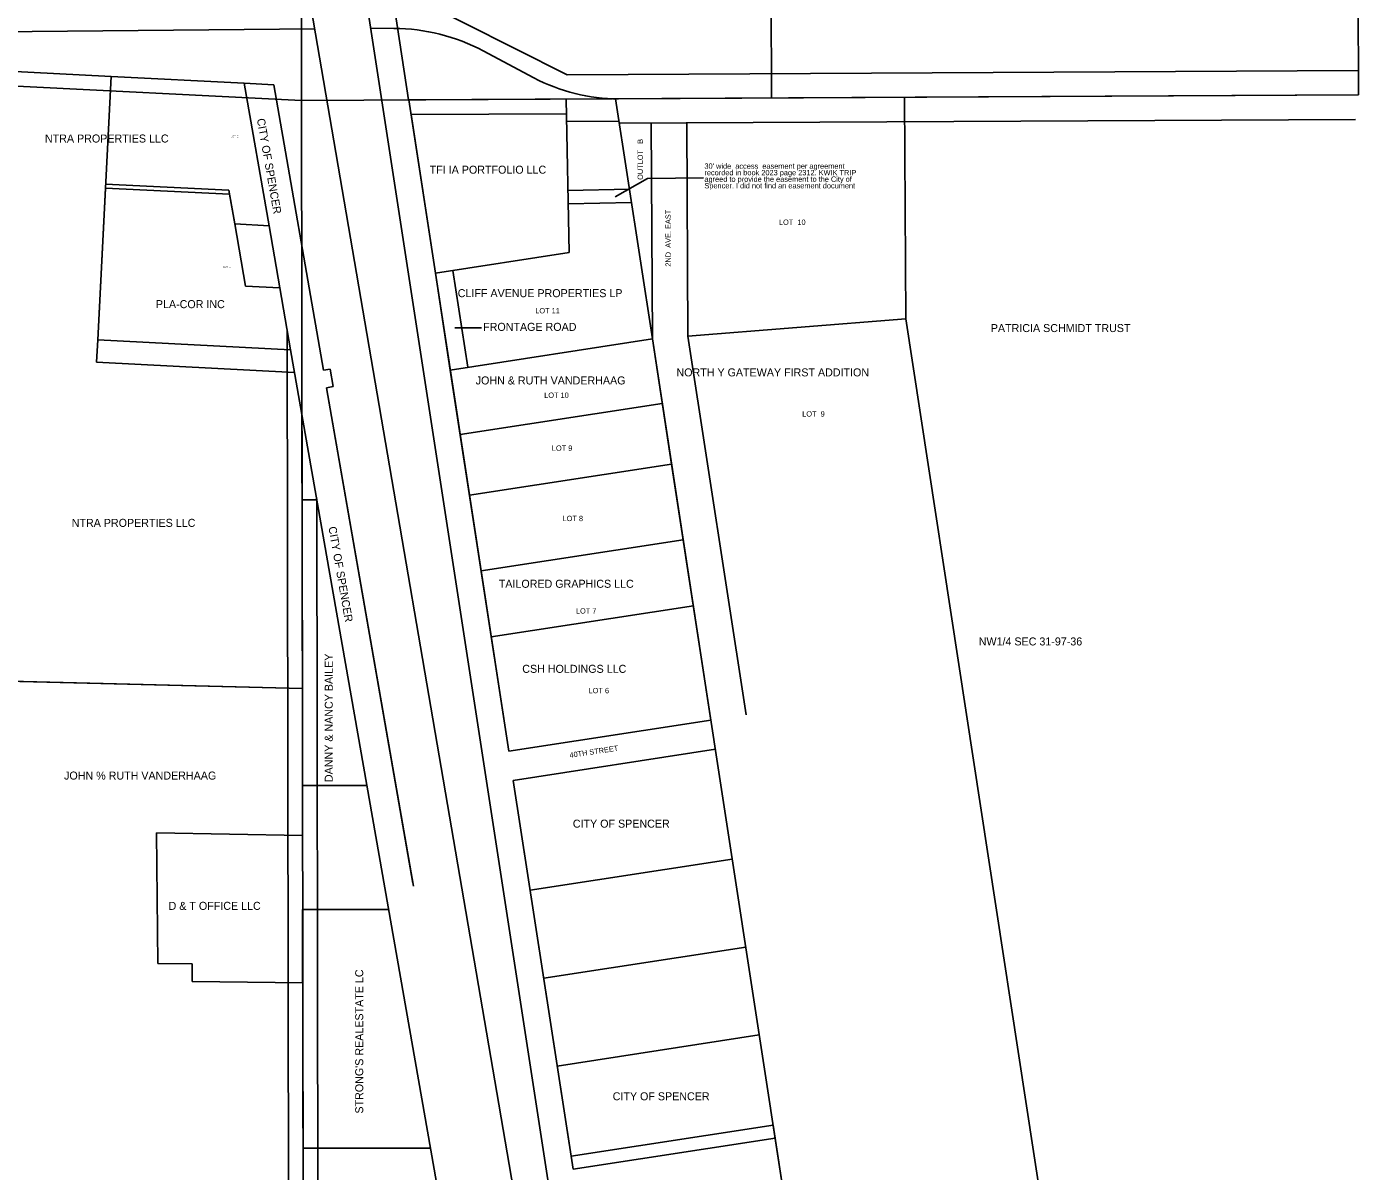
# Model space of a CAD drawing. Extents: x 11521219 to 11528920, y 9587418 to 9599499.
# Drawn here: x 11525924 to 11528920, y 9591637 to 9594212 of the extents above; entities that cross this region are included whole.
import ezdxf

# ---------------------------------------------------------------- set-up
doc = ezdxf.new("R2010")
doc.units = 0
for name, color, linetype in [('Alignment', 7, 'Continuous'), ('DisROW Existing', 7, 'Continuous'), ('DisROW Lot Lines', 7, 'Continuous'), ('DisROW Property Lines', 7, 'Continuous'), ('DisROW Survey', 7, 'Continuous'), ('Section Lines', 7, 'Continuous'), ('Text', 7, 'Continuous')]:
    doc.layers.add(name, color=color, linetype=linetype)

msp = doc.modelspace()

# ---------------------------------------------------------------- linework, layer by layer
at = {"layer": 'Alignment'}
for p, q in [((11527252.3, 9590607.6), (11526645, 9594551)), ((11527165.7, 9590741), (11526539.8, 9594397.6)), ((11523871.9, 9594181.4), (11526572.4, 9594207.2)), ((11526697.8, 9594208.3), (11526750.3, 9594208.1)), ((11526951.3, 9594157.5), (11527065.3, 9594096.7)), ((11527255.7, 9594049.6), (11528919.9, 9594058.4))]:
    msp.add_line(p, q, dxfattribs=at)
for centre, radius, start, end in [((11526748.9, 9593778.1), 430, 61.9248, 89.8166), ((11527256.1, 9594459.6), 410, 242.2771, 269.9507)]:
    msp.add_arc(centre, radius, start, end, dxfattribs=at)
at = {"layer": 'DisROW Existing'}
for p, q in [((11526743.9, 9594303.4), (11527140.1, 9594104)), ((11525869.3, 9594112.3), (11526113.9, 9594099.8)), ((11527140.1, 9594104), (11528919.7, 9594113.4)), ((11526113.9, 9594099.8), (11526413.5, 9594084.6)), ((11526413.5, 9594084.6), (11526480.2, 9594081.1)), ((11526480.2, 9594081.1), (11526592, 9593439.4)), ((11526788.9, 9594014.2), (11527138.5, 9594016)), ((11526843.7, 9593657.6), (11526788.9, 9594014.2)), ((11527138.5, 9594016), (11527138.8, 9593999)), ((11527256.5, 9593999.6), (11527138.8, 9593999)), ((11527257.3, 9593994.6), (11528913.3, 9594003.4)), ((11526877.2, 9593439.7), (11526843.7, 9593657.6)), ((11526510.2, 9593529.3), (11526513.1, 9591401.2)), ((11526592, 9593439.4), (11526606.7, 9593441.9)), ((11526606.7, 9593441.9), (11526613.7, 9593402.5)), ((11526877.2, 9593439.7), (11527008.9, 9592582.2)), ((11526613.7, 9593402.5), (11526598.9, 9593400)), ((11526598.9, 9593400), (11526794.2, 9592278.7)), ((11526576.8, 9593149.7), (11526579.1, 9591401.4)), ((11527463.5, 9592651.9), (11527008.9, 9592582.2)), ((11527018.9, 9592516.8), (11527473.6, 9592586.7)), ((11527153.2, 9591642.1), (11527018.9, 9592516.8))]:
    msp.add_line(p, q, dxfattribs=at)
at = {"layer": 'DisROW Lot Lines'}
for p, q in [((11526083.9, 9593507.3), (11526113.9, 9594099.8)), ((11526113.9, 9594099.8), (11526413.5, 9594084.6)), ((11526413.5, 9594084.6), (11526469.4, 9593764.4)), ((11527137.8, 9594049), (11527144.5, 9593703.8)), ((11527331.8, 9593509.7), (11527248.9, 9594049.6)), ((11527329.2, 9593995), (11527331.8, 9593509.7)), ((11527409.2, 9593995.4), (11527411.8, 9593516)), ((11526379.2, 9593844.1), (11526101.6, 9593858.1)), ((11526379.2, 9593844.1), (11526392.5, 9593768.2)), ((11526469.4, 9593764.4), (11526392.5, 9593768.2)), ((11526469.4, 9593764.4), (11526517.9, 9593485.1)), ((11527144.5, 9593703.8), (11526843.7, 9593657.6)), ((11526843.7, 9593657.6), (11527008.9, 9592582.2)), ((11527901.7, 9593554.7), (11527411.8, 9593515.9)), ((11526517.9, 9593485.1), (11526083.9, 9593507.3)), ((11527331.8, 9593509.7), (11526877.2, 9593439.7)), ((11527375.1, 9593227.9), (11527331.8, 9593509.7)), ((11527331.8, 9593509.7), (11527463.5, 9592651.9)), ((11527411.8, 9593516), (11527542.6, 9592664)), ((11527354.1, 9593364.4), (11526899.5, 9593294.4)), ((11527375.1, 9593227.9), (11526920.4, 9593158.1)), ((11527654.7, 9591407), (11527375.1, 9593227.9)), ((11526946.5, 9592988.1), (11527401.2, 9593057.9)), ((11526969.3, 9592839.8), (11527424, 9592909.6)), ((11527463.5, 9592651.9), (11527008.9, 9592582.2)), ((11527018.9, 9592516.8), (11527473.6, 9592586.7)), ((11527018.9, 9592516.8), (11527153.2, 9591642.1)), ((11527056.9, 9592269.8), (11527511.5, 9592339.6)), ((11527087.2, 9592072.1), (11527541.9, 9592141.9)), ((11527117.6, 9591874.4), (11527572.2, 9591944.2)), ((11527153.2, 9591642.1), (11527607.9, 9591712))]:
    msp.add_line(p, q, dxfattribs=at)
at = {"layer": 'DisROW Property Lines'}
for p, q in [((11528919.9, 9594058.4), (11528913, 9596702.5)), ((11526743.9, 9594303.4), (11526783.4, 9594047.1)), ((11525869.3, 9594112.3), (11526113.9, 9594099.8)), ((11526113.9, 9594099.8), (11526413.5, 9594084.6)), ((11526413.5, 9594084.6), (11526469.4, 9593764.4)), ((11526413.5, 9594084.6), (11526480.2, 9594081.1)), ((11526480.2, 9594081.1), (11526592, 9593439.4)), ((11526783.4, 9594047.1), (11528919.9, 9594058.4)), ((11526783.9, 9594047.1), (11526843.7, 9593657.6)), ((11527144.5, 9593703.8), (11527137.8, 9594049)), ((11527248.9, 9594049.6), (11527331.8, 9593509.7)), ((11527901.7, 9593554.7), (11527899, 9594053)), ((11527138.8, 9593999), (11527256.5, 9593999.6)), ((11526101.2, 9593849.1), (11526083.9, 9593507.3)), ((11526380.8, 9593834.9), (11526101.2, 9593849.1)), ((11526380.8, 9593834.9), (11526392.5, 9593768.2)), ((11526416.8, 9593628.7), (11526392.5, 9593768.2)), ((11526469.4, 9593764.4), (11526493.6, 9593624.9)), ((11526843.7, 9593657.6), (11527144.5, 9593703.8)), ((11526877.2, 9593439.7), (11526843.7, 9593657.6)), ((11526916.7, 9593445.8), (11526883.2, 9593663.6)), ((11526493.6, 9593624.9), (11526416.8, 9593628.7)), ((11526493.6, 9593624.9), (11526517.9, 9593485.1)), ((11528231, 9591410.6), (11527901.7, 9593554.7)), ((11526083.9, 9593507.3), (11526081.3, 9593457.3)), ((11527331.8, 9593509.7), (11526877.2, 9593439.7)), ((11527401.2, 9593057.9), (11527331.8, 9593509.7)), ((11526995.6, 9590762), (11526517.9, 9593485.1)), ((11526526.8, 9593434.4), (11526081.3, 9593457.3)), ((11526592, 9593439.4), (11526606.7, 9593441.9)), ((11526606.7, 9593441.9), (11526613.7, 9593402.5)), ((11526877.2, 9593439.7), (11526946.5, 9592988.1)), ((11526613.7, 9593402.5), (11526598.9, 9593400)), ((11526598.9, 9593400), (11526793, 9592285.9)), ((11526543.5, 9593339.3), (11526544.3, 9592723.2)), ((11526577.1, 9593147.9), (11526543.8, 9593147.8)), ((11526946.5, 9592988.1), (11527401.2, 9593057.9)), ((11527463.5, 9592651.9), (11527401.2, 9593057.9)), ((11526946.5, 9592988.1), (11527008.9, 9592582.2)), ((11526969.3, 9592839.8), (11527424, 9592909.6)), ((11526544.3, 9592723.2), (11525878.7, 9592739.8)), ((11526544.8, 9592393.1), (11526544.3, 9592723)), ((11527008.9, 9592582.2), (11527463.5, 9592651.9)), ((11527473.6, 9592586.7), (11527018.9, 9592516.8)), ((11527148.7, 9591671.8), (11527018.9, 9592516.8)), ((11526689.8, 9592505.4), (11526544.6, 9592505.2)), ((11526544.8, 9592393.1), (11526216, 9592399)), ((11526219, 9592105), (11526216, 9592399)), ((11526738.7, 9592226.5), (11526545, 9592226.3)), ((11526545, 9592226.3), (11526546.1, 9591401.3)), ((11526296.2, 9592104.1), (11526219, 9592105)), ((11526296.2, 9592104.1), (11526296.2, 9592064.1)), ((11526545.2, 9592061.2), (11526296.2, 9592064.1)), ((11527148.7, 9591671.8), (11527603.3, 9591741.7)), ((11527603.3, 9591741.7), (11527654.7, 9591407)), ((11526832.9, 9591689.6), (11526545.7, 9591689.3))]:
    msp.add_line(p, q, dxfattribs=at)
at = {"layer": 'DisROW Survey'}
for p, q in [((11527141.8, 9593843.8), (11527280.1, 9593846.4)), ((11527142.4, 9593813.8), (11527284.7, 9593816.4)), ((11526947.2, 9593535), (11526887.1, 9593535)), ((11526877.2, 9593439.7), (11526920.4, 9593158.1)), ((11526920.4, 9593158.1), (11527008.9, 9592582.2))]:
    msp.add_line(p, q, dxfattribs=at)
at = {"layer": 'Section Lines'}
for p, q in [((11526542.5, 9594045.8), (11526542.9, 9596688)), ((11527599.9, 9594051.4), (11527593, 9596694.4)), ((11526542.5, 9594045.8), (11523871.9, 9594181.4)), ((11526542.5, 9594045.8), (11528919.9, 9594058.4)), ((11526546.1, 9591401.3), (11526542.5, 9594045.8)), ((11523881.5, 9592791.3), (11526544.3, 9592723.2))]:
    msp.add_line(p, q, dxfattribs=at)
at = {"layer": 'Text'}
for p, q in [((11527320.9, 9593870.5), (11527248.2, 9593829.5)), ((11527446.9, 9593872.3), (11527320.9, 9593870.5))]:
    msp.add_line(p, q, dxfattribs=at)

# ---------------------------------------------------------------- texts
for s, height, rotation, p in [('CITY OF SPENCER', 18, 280, (11526441.9, 9594004.1)), ('OUTLOT   B', 12, 90, (11527310.4, 9593867.4)), ('2ND  AVE. EAST', 12, 90, (11527373.2, 9593672.2)), ('CITY OF SPENCER', 18, 280, (11526602.8, 9593086.2)), ('DANNY & NANCY BAILEY', 18, 90, (11526612.7, 9592512.9)), ('40TH STREET', 12, 8.5, (11527146.3, 9592567.4)), ("STRONG'S REALESTATE LC", 18, 90, (11526681.3, 9591767.4))]:
    msp.add_text(s, height=height, rotation=rotation, dxfattribs=at).set_placement(p)
for s, height, p in [('NTRA PROPERTIES LLC', 18, (11525965.3, 9593951.4)), ('LOT  2', 3.9, (11526383.9, 9593963.4)), ('TFI IA PORTFOLIO LLC', 18, (11526830.8, 9593881.3)), ("30' wide  access  easement per agreement", 12, (11527448.8, 9593892.4)), ('agreed to provide the easement to the City of', 12, (11527448.8, 9593863)), ('recorded in book 2023 page 2312. KWIK TRIP', 12, (11527448.8, 9593877.7)), ('Spencer. I did not find an easement document', 12, (11527448.8, 9593848.3)), ('LOT  10', 12, (11527616.5, 9593766.2)), ('LOT  1', 3.9, (11526366.5, 9593670.1)), ('PLA-COR INC', 18, (11526214.8, 9593578.9)), ('CLIFF AVENUE PROPERTIES LP', 18, (11526893.9, 9593603.6)), ('LOT 11', 12, (11527068.3, 9593567.1)), ('FRONTAGE ROAD', 18, (11526951, 9593527.8)), ('PATRICIA SCHMIDT TRUST', 18, (11528093, 9593525.1)), ('JOHN & RUTH VANDERHAAG', 18, (11526934.3, 9593407.3)), ('NORTH Y GATEWAY FIRST ADDITION', 18, (11527385.9, 9593425.4)), ('LOT 10', 12, (11527088.4, 9593377.1)), ('LOT  9', 12, (11527668.8, 9593335)), ('LOT 9', 12, (11527105.6, 9593258)), ('NTRA PROPERTIES LLC', 18, (11526025.5, 9593087)), ('LOT 8', 12, (11527129.7, 9593099.9)), ('TAILORED GRAPHICS LLC', 18, (11526986.2, 9592950)), ('LOT 7', 12, (11527159.8, 9592892)), ('NW1/4 SEC 31-97-36', 18, (11528065.9, 9592820.3)), ('CSH HOLDINGS LLC', 18, (11527039, 9592758.7)), ('LOT 6', 12, (11527188.3, 9592712.8)), ('JOHN % RUTH VANDERHAAG', 18, (11526008.3, 9592518.6)), ('CITY OF SPENCER', 18, (11527152.8, 9592410.5)), ('D & T OFFICE LLC', 18, (11526243.4, 9592225.6)), ('CITY OF SPENCER', 18, (11527242.5, 9591797.3))]:
    msp.add_text(s, height=height, dxfattribs=at).set_placement(p)

doc.saveas('drawing.dxf')
